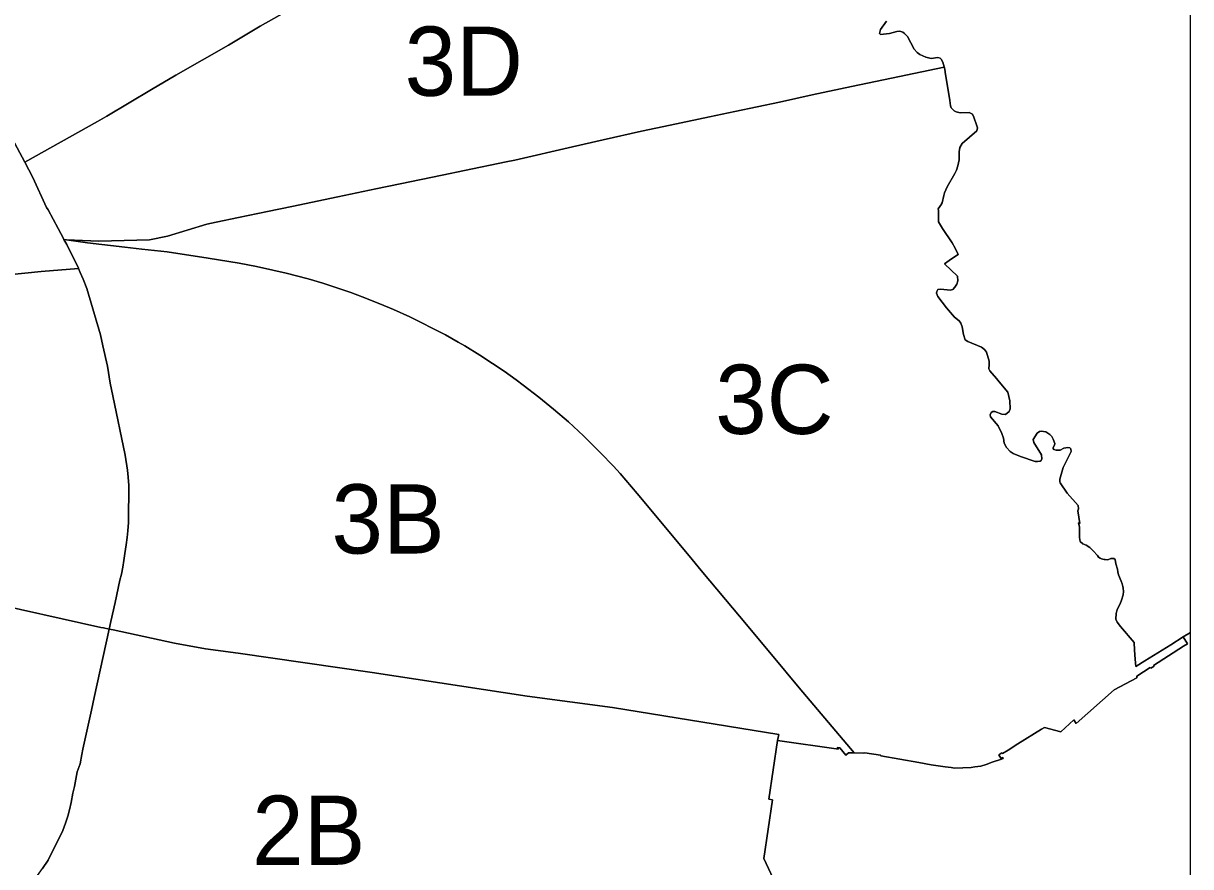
# Model space of a CAD drawing. Extents: x 152750 to 166250, y 378996 to 390000.
# Drawn here: x 162877 to 166250, y 382190 to 384626 of the extents above; entities that cross this region are included whole.
import ezdxf

# ---------------------------------------------------------------- set-up
doc = ezdxf.new("R2010")
doc.units = 0
doc.layers.add('BLT_Nummers', color=7, linetype='Continuous')
doc.layers.add('BLT_Shapes', color=7, linetype='Continuous')

msp = doc.modelspace()

# ---------------------------------------------------------------- linework, layer by layer
at = {"layer": 'BLT_Shapes'}
for p, q in [((165409.8, 384603.6), (165400.8, 384603.2)), ((165467.2, 384536), (165459.4, 384541.9)), ((165385.8, 384468.2), (165537.9, 384499.5)), ((165533.7, 384514.2), (165528.9, 384523.1)), ((165539.5, 384493.6), (165537.9, 384499.5)), ((165269.5, 384444.1), (165385.8, 384468.2)), ((165553.9, 384403.7), (165540.9, 384485)), ((165155.9, 384420), (165269.5, 384444.1)), ((165556.2, 384388.3), (165553.9, 384403.7)), ((165558.2, 384382.6), (165556.2, 384388.3)), ((165589.9, 384279.1), (165631.7, 384316)), ((165631.7, 384316), (165634.1, 384325)), ((164463.2, 384269.8), (164551.9, 384289.7)), ((165583.2, 384267.5), (165589.9, 384279.1)), ((162880.5, 384225.3), (162903.9, 384180.6)), ((165546.7, 384154.2), (165568.7, 384192.4)), ((163966, 384163.1), (164086.8, 384187.9)), ((163652.7, 384097.4), (163785.6, 384125.3)), ((165529.8, 384104.2), (165530.3, 384105.2)), ((165530.3, 384105.2), (165532, 384108.1)), ((165521.6, 384052.6), (165520.9, 384085.6)), ((165532.4, 384033.7), (165521.6, 384052.6)), ((163001.2, 384001.3), (162994.1, 384001.6)), ((162994.1, 384001.6), (163001.2, 384001.3)), ((163001.2, 384001.3), (163094.9, 383997.5)), ((165564.5, 383949.7), (165577.8, 383959.1)), ((163500.2, 383933.6), (163550, 383923.9)), ((163550, 383923.9), (163597.7, 383913.6)), ((165539.1, 383931.7), (165552.5, 383941.2)), ((165552.5, 383941.2), (165564.5, 383949.7)), ((163035.7, 383918.7), (162928.6, 383909.3)), ((163036.4, 383918.8), (163035.7, 383918.7)), ((163597.7, 383913.6), (163635.7, 383904.5)), ((163049.4, 383887.3), (163059.9, 383860.1)), ((163059.9, 383860.1), (163099.2, 383726.8)), ((163741.9, 383875.8), (163788.4, 383860.8)), ((165519, 383857.9), (165528.4, 383858.8)), ((165528.4, 383858.8), (165554.7, 383855.9)), ((165554.7, 383855.9), (165562.7, 383857.8)), ((164024.3, 383763.4), (164062.1, 383744.4)), ((165585.7, 383760), (165581.3, 383767)), ((165589.3, 383750), (165585.7, 383760)), ((165654.4, 383683.9), (165646, 383691.2)), ((165660.2, 383676.1), (165654.4, 383683.9)), ((164232.8, 383644.1), (164266, 383621.7)), ((164266, 383621.7), (164300.8, 383597)), ((165669.4, 383622.3), (165666.5, 383628.4)), ((164300.8, 383597), (164321.2, 383581.4)), ((165670.7, 383496), (165673.1, 383502)), ((165673.1, 383502), (165678.2, 383505.4)), ((165678.2, 383505.4), (165684, 383504.9)), ((165684, 383504.9), (165704.4, 383497.8)), ((165704.4, 383497.8), (165715.4, 383496.5)), ((165715.4, 383496.5), (165725.9, 383505)), ((165725.9, 383505), (165728.2, 383513.3)), ((164495.1, 383435.3), (164544.7, 383385.3)), ((165852.7, 383398.4), (165852.5, 383401.6)), ((165854.5, 383395.5), (165852.7, 383398.4)), ((165861.7, 383393.5), (165854.5, 383395.5)), ((165873.2, 383393.4), (165861.7, 383393.5)), ((165883.4, 383398.9), (165873.2, 383393.4)), ((165894.9, 383401.3), (165883.4, 383398.9)), ((165900.7, 383400.1), (165894.9, 383401.3)), ((165903.4, 383397.3), (165900.7, 383400.1)), ((165820.4, 383368.8), (165817.9, 383363.4)), ((164601.1, 383325.7), (164650.6, 383267.9)), ((163180.4, 383184.8), (163178.6, 383160.6)), ((163180.2, 383207.9), (163180.4, 383184.8)), ((163178.6, 383160.6), (163176.2, 383141.4)), ((165984.1, 383084.6), (165980.9, 383089.1)), ((165988.5, 383081.1), (165984.1, 383084.6)), ((166028, 383080.9), (166019.4, 383080.3)), ((166031.5, 383078.1), (166028, 383080.9)), ((163163.8, 383055.1), (163160, 383035)), ((166002.7, 383077.4), (166000, 383077.9)), ((166034, 383065), (166031.5, 383078.1)), ((163160, 383035), (163155.9, 383017.8)), ((166054.1, 383000), (166052.4, 383007.6)), ((166034.1, 382905.3), (166034.9, 382921.6)), ((166034.9, 382921.6), (166036.8, 382929.1)), ((163124.9, 382876.6), (163081.1, 382679)), ((163129.7, 382898.4), (163124.9, 382876.6)), ((166086.5, 382837.7), (166047.1, 382884.5)), ((166240.7, 382834.4), (166228.6, 382853.8)), ((166143.1, 382771.7), (166229.2, 382827.4)), ((166229.2, 382827.4), (166240.7, 382834.4)), ((163497.5, 382806.9), (163884.9, 382751.3)), ((166091.5, 382768.3), (166089.9, 382789.7)), ((163884.9, 382751.3), (164332.9, 382682.8)), ((166094.9, 382741), (166133.2, 382765.3)), ((166094.8, 382735.7), (166094.9, 382741)), ((165277.2, 382519.1), (165118.8, 382707.3)), ((165818.7, 382587.2), (165827.3, 382592.1)), ((165030.8, 382385.2), (165056.4, 382554.4)), ((163045.7, 382514.5), (163041, 382487.9)), ((163048.3, 382529.9), (163045.7, 382514.5)), ((165261.7, 382519.5), (165277.2, 382519.1)), ((165277.3, 382519.1), (165304.3, 382518.5)), ((165500.5, 382485), (165540.4, 382479.1)), ((165540.4, 382479.1), (165557.5, 382477)), ((165615.3, 382476.9), (165626.7, 382478.3)), ((165703.4, 382500.5), (165707.8, 382502.7)), ((163014.5, 382375.9), (163009.8, 382354.3)), ((163020.1, 382402.5), (163014.5, 382375.9)), ((165017, 382214.3), (165041.9, 382383.4)), ((163004.8, 382336.6), (162998.6, 382316.2)), ((163009.8, 382354.3), (163004.8, 382336.6)), ((162948.6, 382208.9), (162932.1, 382185.3))]:
    msp.add_line(p, q, dxfattribs=at)
for points in [[(165370.7, 384632.6), (165353.9, 384608.6), (165350.4, 384596.6), (165353.5, 384594.1), (165379.5, 384597.2), (165400.8, 384603.2), (165409.8, 384603.6), (165418.3, 384600.9), (165423.4, 384597.2), (165432.2, 384588.1), (165450.8, 384552), (165459.4, 384541.9), (165467.2, 384536), (165484.4, 384528.6), (165500, 384524.7), (165519.1, 384527.6), (165526.3, 384525.9), (165528.9, 384523.1), (165533.7, 384514.2), (165537.5, 384500.7), (165539.5, 384493.6), (165540.8, 384485.3), (165540.9, 384485), (165553.9, 384403.7), (165556.2, 384388.3), (165558.2, 384382.6), (165566.4, 384373.7), (165571.9, 384371.1), (165584.1, 384368.2), (165609.7, 384369.2), (165619.7, 384364), (165623.1, 384355), (165632.4, 384330.6), (165634.1, 384325), (165631.7, 384316), (165589.9, 384279.1), (165583.2, 384267.5), (165581.2, 384255.3), (165581, 384250), (165580.7, 384232.4), (165577.5, 384215.2), (165573.2, 384202), (165568.7, 384192.4), (165546.7, 384154.2), (165539.1, 384136.6), (165537.2, 384129.3), (165532, 384108.1), (165530.3, 384105.2), (165529.8, 384104.2), (165520.8, 384090.9), (165520.9, 384085.6), (165521.6, 384052.6), (165532.4, 384033.7), (165560.8, 383992.5), (165569, 383977.4), (165569.4, 383976.7), (165577.8, 383959.1), (165564.5, 383949.7), (165552.5, 383941.2), (165539.1, 383931.7), (165576.1, 383896.1), (165577.2, 383883), (165574.1, 383872.9), (165568.6, 383864), (165562.7, 383857.8), (165554.7, 383855.9), (165528.4, 383858.8), (165519, 383857.9), (165516.2, 383851.5), (165515.6, 383847), (165519.6, 383837.8), (165544.7, 383804.5), (165567.9, 383777.4), (165581.3, 383767), (165585.7, 383760), (165589.3, 383750), (165593.6, 383727.6), (165598.1, 383712.6), (165605.9, 383707), (165646, 383691.2), (165654.4, 383683.9), (165660.2, 383676.1), (165667.4, 383650.3), (165668.1, 383640.7), (165666.5, 383628.4), (165669.4, 383622.3), (165689.4, 383600), (165696.8, 383590.6), (165721.3, 383560.9), (165727.4, 383536.1), (165728.2, 383513.3), (165725.9, 383505), (165715.4, 383496.5), (165704.4, 383497.8), (165684, 383504.9), (165678.2, 383505.4), (165673.1, 383502), (165670.7, 383496), (165671.9, 383489.4), (165693.8, 383463.5), (165704.6, 383441.2), (165708.9, 383428.2), (165711.4, 383413.7), (165718.2, 383401.6), (165728.4, 383389.5), (165737.4, 383383.6), (165758.5, 383375), (165800.7, 383361), (165807.4, 383360.3), (165814.8, 383361.3), (165817.9, 383363.4), (165820.4, 383368.8), (165818.6, 383379.9), (165796.5, 383415.8), (165795.3, 383424.2), (165806.4, 383442.8), (165813.2, 383447.7), (165818.3, 383448.6), (165831.9, 383446.5), (165843, 383439.1), (165848.6, 383432.9), (165852.9, 383425.7), (165857.1, 383412.3), (165856.2, 383408.1), (165852.5, 383401.6), (165852.7, 383398.4), (165854.5, 383395.5), (165861.7, 383393.5), (165873.2, 383393.4), (165883.4, 383398.9), (165894.9, 383401.3), (165900.7, 383400.1), (165903.4, 383397.3), (165904.8, 383389.7), (165881.7, 383343), (165871.8, 383309.3), (165871.8, 383302.9), (165872.6, 383299), (165893, 383269.4), (165924.9, 383233.8), (165925.9, 383223.6), (165923.5, 383218), (165929.5, 383181.3), (165926.3, 383183.1), (165928.3, 383171.5), (165928.5, 383141.1), (165930.9, 383129.8), (165938.4, 383123.1), (165947.9, 383118.6), (165958.2, 383112.5), (165968.5, 383102.9), (165980.9, 383089.1), (165984.1, 383084.6), (165988.5, 383081.1), (165992.8, 383079.1), (166000, 383077.9), (166002.7, 383077.4), (166010.5, 383076.8), (166019.4, 383080.3), (166028, 383080.9), (166031.5, 383078.1), (166034, 383065), (166038.7, 383049.8), (166039.4, 383041.9), (166041.5, 383033), (166048.9, 383015.2), (166052.4, 383007.6), (166054.1, 383000), (166055.3, 382994.5), (166055.9, 382985.4), (166054.8, 382975.7), (166050.3, 382960.3), (166045.9, 382949.2), (166038.7, 382935.2), (166036.8, 382929.1), (166034.9, 382921.6), (166034.1, 382905.3), (166037.2, 382896.4), (166047.1, 382884.5), (166086.5, 382837.7), (166087.9, 382815.9), (166089.9, 382789.7), (166091.5, 382768.3), (166117.4, 382784.5), (166192.9, 382831.5), (166228.6, 382853.8), (166250, 382867.2), (166250, 386812.5)], [(165034.1, 385170.8), (164943.2, 385157.8), (164918.8, 385154.9), (164764.2, 385130.5), (164713.3, 385120.8), (164611.1, 385098.7), (164530.5, 385081), (164429.9, 385049.5), (164371.3, 385029.6), (164261.9, 384987.6), (164212.2, 384967.1), (164157.5, 384943.4), (164090.1, 384911.9), (164005, 384866), (163859.2, 384786.4), (163561.4, 384617.8), (163469.7, 384563.7), (163317.7, 384476.3), (163247.4, 384435), (163117.5, 384358.5), (163090.9, 384342.8), (162880.5, 384225.3)], [(163247.4, 384435), (163317.7, 384476.3), (163469.7, 384563.7), (163561.4, 384617.8), (163859.2, 384786.4), (164005, 384866), (164090.1, 384911.9), (164157.5, 384943.4)], [(165350.4, 384596.6), (165353.9, 384608.6), (165370.7, 384632.6)], [(165400.8, 384603.2), (165379.5, 384597.2), (165353.5, 384594.1), (165350.4, 384596.6)], [(165423.4, 384597.2), (165418.3, 384600.9), (165409.8, 384603.6)], [(165459.4, 384541.9), (165450.8, 384552), (165432.2, 384588.1), (165423.4, 384597.2)], [(165528.9, 384523.1), (165526.3, 384525.9), (165519.1, 384527.6), (165500, 384524.7), (165484.4, 384528.6), (165467.2, 384536)], [(165537.9, 384499.5), (165385.8, 384468.2), (165269.5, 384444.1), (165155.9, 384420), (165062.2, 384398.7), (164933, 384371.7), (164859.2, 384356.1), (164745.7, 384331.9), (164662.6, 384315.3), (164551.9, 384289.7), (164463.2, 384269.8), (164296.9, 384231), (164272.2, 384226.4), (164151.9, 384201.7), (164086.8, 384187.9), (163966, 384163.1), (163895.4, 384148.3), (163785.6, 384125.3), (163652.7, 384097.4), (163581.9, 384082.8), (163498.2, 384065.4), (163434, 384052), (163407, 384045.9), (163292.9, 384011.8), (163241.1, 384001.1), (163094.9, 383997.5), (163001.2, 384001.3)], [(165537.9, 384499.5), (165537.5, 384500.7), (165533.7, 384514.2)], [(165540.9, 384485), (165540.8, 384485.3), (165539.5, 384493.6)], [(162880.5, 384225.3), (163090.9, 384342.8), (163117.5, 384358.5), (163247.4, 384435)], [(164933, 384371.7), (165062.2, 384398.7), (165155.9, 384420)], [(162783.5, 384391.8), (162801.7, 384361.3), (162836.7, 384307.9), (162880.5, 384225.3)], [(164745.7, 384331.9), (164859.2, 384356.1), (164933, 384371.7)], [(165609.7, 384369.2), (165584.1, 384368.2), (165571.9, 384371.1), (165566.4, 384373.7), (165558.2, 384382.6)], [(165623.1, 384355), (165619.7, 384364), (165609.7, 384369.2)], [(164551.9, 384289.7), (164662.6, 384315.3), (164745.7, 384331.9)], [(165634.1, 384325), (165632.4, 384330.6), (165623.1, 384355)], [(162880.5, 384225.3), (162836.7, 384307.9)], [(164272.2, 384226.4), (164296.9, 384231), (164463.2, 384269.8)], [(165577.5, 384215.2), (165580.7, 384232.4), (165581, 384250), (165581.2, 384255.3), (165583.2, 384267.5)], [(164086.8, 384187.9), (164151.9, 384201.7), (164272.2, 384226.4)], [(162994.1, 384001.6), (162992.4, 384004.7), (162977, 384033.3), (162947.9, 384087.4), (162943.4, 384094.5), (162903.9, 384180.6), (162880.5, 384225.3)], [(165568.7, 384192.4), (165573.2, 384202), (165577.5, 384215.2)], [(162903.9, 384180.6), (162943.4, 384094.5), (162947.9, 384087.4)], [(163785.6, 384125.3), (163895.4, 384148.3), (163966, 384163.1)], [(165532, 384108.1), (165537.2, 384129.3), (165539.1, 384136.6), (165546.7, 384154.2)], [(163498.2, 384065.4), (163581.9, 384082.8), (163652.7, 384097.4)], [(165520.9, 384085.6), (165520.8, 384090.9), (165529.8, 384104.2)], [(162947.9, 384087.4), (162977, 384033.3), (162992.4, 384004.7), (162994.1, 384001.6)], [(163407, 384045.9), (163434, 384052), (163498.2, 384065.4)], [(163094.9, 383997.5), (163241.1, 384001.1), (163292.9, 384011.8), (163407, 384045.9)], [(165569, 383977.4), (165560.8, 383992.5), (165532.4, 384033.7)], [(163036.4, 383918.8), (163017.9, 383956.3), (163011.2, 383969.7), (163002.1, 383987.4), (162994.1, 384001.6)], [(162994.1, 384001.6), (163002.1, 383987.4), (163011.2, 383969.7), (163017.9, 383956.3), (163036.4, 383918.8)], [(165118.8, 382707.3), (165038.8, 382803.3), (164946.5, 382913.5), (164905.9, 382962.4), (164835.9, 383045.9), (164809.4, 383077.6), (164719, 383186.6), (164650.6, 383267.9), (164601.1, 383325.7), (164581.9, 383347.3), (164544.7, 383385.3), (164495.1, 383435.3), (164452.2, 383474.9), (164409, 383512.1), (164366.3, 383546.9), (164321.2, 383581.4), (164300.8, 383597), (164266, 383621.7), (164232.8, 383644.1), (164195.8, 383667.8), (164152.1, 383694.4), (164132.9, 383705.6), (164096.3, 383726.8), (164062.1, 383744.4), (164024.3, 383763.4), (163993.9, 383778.6), (163946, 383799.6), (163907, 383816.4), (163856, 383836.6), (163823, 383848.9), (163788.4, 383860.8), (163741.9, 383875.8), (163699.4, 383888.3), (163635.7, 383904.5), (163597.7, 383913.6), (163550, 383923.9), (163500.2, 383933.6), (163410.3, 383948.5), (163291.9, 383966.2), (163218.9, 383974.4), (163170.3, 383979.8), (163061.7, 383992.8), (163001.2, 384001.3)], [(163001.2, 384001.3), (163061.7, 383992.8), (163170.3, 383979.8)], [(163170.3, 383979.8), (163218.9, 383974.4), (163291.9, 383966.2)], [(163291.9, 383966.2), (163410.3, 383948.5), (163500.2, 383933.6)], [(165577.8, 383959.1), (165569.4, 383976.7), (165569, 383977.4)], [(165574.1, 383872.9), (165577.2, 383883), (165576.1, 383896.1), (165539.1, 383931.7)], [(162606.3, 383864.8), (162744, 383890), (162833.8, 383899.6), (162928.6, 383909.3), (163035.7, 383918.7), (163036.4, 383918.8)], [(162928.6, 383909.3), (162833.8, 383899.6), (162744, 383890), (162606.3, 383864.8)], [(163124.9, 382876.6), (163129.7, 382898.4), (163141.7, 382953.1), (163155.9, 383017.8), (163160, 383035), (163163.8, 383055.1), (163167.4, 383075.2), (163170.3, 383095.3), (163173.9, 383120.1), (163176.2, 383141.4), (163178.6, 383160.6), (163180.4, 383184.8), (163180.2, 383207.9), (163181.1, 383272.3), (163181.4, 383291.5), (163179.9, 383315.2), (163177.3, 383335.6), (163171.1, 383378.7), (163135.3, 383550.2), (163127.1, 383587.4), (163120, 383635.8), (163106.7, 383694.7), (163099.2, 383726.8), (163059.9, 383860.1), (163049.4, 383887.3), (163041.2, 383906.8), (163035.7, 383918.7)], [(163035.7, 383918.7), (163041.2, 383906.8), (163049.4, 383887.3)], [(163635.7, 383904.5), (163699.4, 383888.3), (163741.9, 383875.8)], [(163788.4, 383860.8), (163823, 383848.9), (163856, 383836.6)], [(165515.6, 383847), (165516.2, 383851.5), (165519, 383857.9)], [(165562.7, 383857.8), (165568.6, 383864), (165574.1, 383872.9)], [(163856, 383836.6), (163907, 383816.4), (163946, 383799.6), (163993.9, 383778.6), (164024.3, 383763.4)], [(165581.3, 383767), (165567.9, 383777.4), (165544.7, 383804.5), (165519.6, 383837.8), (165515.6, 383847)], [(163099.2, 383726.8), (163106.7, 383694.7), (163120, 383635.8), (163127.1, 383587.4)], [(164062.1, 383744.4), (164096.3, 383726.8), (164132.9, 383705.6), (164152.1, 383694.4), (164195.8, 383667.8), (164232.8, 383644.1)], [(165598.1, 383712.6), (165593.6, 383727.6), (165589.3, 383750)], [(165646, 383691.2), (165605.9, 383707), (165598.1, 383712.6)], [(165666.5, 383628.4), (165668.1, 383640.7), (165667.4, 383650.3), (165660.2, 383676.1)], [(165728.2, 383513.3), (165727.4, 383536.1), (165721.3, 383560.9), (165696.8, 383590.6), (165689.4, 383600), (165669.4, 383622.3)], [(163127.1, 383587.4), (163135.3, 383550.2), (163171.1, 383378.7)], [(164321.2, 383581.4), (164366.3, 383546.9), (164409, 383512.1)], [(164409, 383512.1), (164452.2, 383474.9), (164495.1, 383435.3)], [(165708.9, 383428.2), (165704.6, 383441.2), (165693.8, 383463.5), (165671.9, 383489.4), (165670.7, 383496)], [(165817.9, 383363.4), (165814.8, 383361.3), (165807.4, 383360.3), (165800.7, 383361), (165758.5, 383375), (165737.4, 383383.6), (165728.4, 383389.5), (165718.2, 383401.6), (165711.4, 383413.7), (165708.9, 383428.2)], [(165857.1, 383412.3), (165852.9, 383425.7), (165848.6, 383432.9), (165843, 383439.1), (165831.9, 383446.5), (165818.3, 383448.6), (165813.2, 383447.7), (165806.4, 383442.8), (165795.3, 383424.2), (165796.5, 383415.8)], [(164544.7, 383385.3), (164581.9, 383347.3), (164601.1, 383325.7)], [(165796.5, 383415.8), (165818.6, 383379.9), (165820.4, 383368.8)], [(165852.5, 383401.6), (165856.2, 383408.1), (165857.1, 383412.3)], [(165871.8, 383302.9), (165871.8, 383309.3), (165881.7, 383343), (165904.8, 383389.7), (165903.4, 383397.3)], [(163171.1, 383378.7), (163177.3, 383335.6), (163179.9, 383315.2), (163181.4, 383291.5), (163181.1, 383272.3), (163180.2, 383207.9)], [(165893, 383269.4), (165872.6, 383299), (165871.8, 383302.9)], [(164650.6, 383267.9), (164719, 383186.6), (164809.4, 383077.6), (164835.9, 383045.9)], [(165923.5, 383218), (165925.9, 383223.6), (165924.9, 383233.8), (165893, 383269.4)], [(165930.9, 383129.8), (165928.5, 383141.1), (165928.3, 383171.5), (165926.3, 383183.1), (165929.5, 383181.3), (165923.5, 383218)], [(163176.2, 383141.4), (163173.9, 383120.1), (163170.3, 383095.3), (163167.4, 383075.2), (163163.8, 383055.1)], [(165980.9, 383089.1), (165968.5, 383102.9), (165958.2, 383112.5), (165947.9, 383118.6), (165938.4, 383123.1), (165930.9, 383129.8)], [(166000, 383077.9), (165992.8, 383079.1), (165988.5, 383081.1)], [(166019.4, 383080.3), (166010.5, 383076.8), (166002.7, 383077.4)], [(164835.9, 383045.9), (164905.9, 382962.4), (164946.5, 382913.5), (165038.8, 382803.3), (165118.8, 382707.3)], [(166041.5, 383033), (166039.4, 383041.9), (166038.7, 383049.8), (166034, 383065)], [(163155.9, 383017.8), (163141.7, 382953.1), (163129.7, 382898.4)], [(166052.4, 383007.6), (166048.9, 383015.2), (166041.5, 383033)], [(163124.9, 382876.6), (163107.8, 382880.2), (163100.9, 382881.7), (162756.1, 382958.4), (162582.8, 382996), (162548.9, 383003.9)], [(166050.3, 382960.3), (166054.8, 382975.7), (166055.9, 382985.4)], [(166055.9, 382985.4), (166055.3, 382994.5), (166054.1, 383000)], [(162756.1, 382958.4), (163100.9, 382881.7), (163107.8, 382880.2), (163124.9, 382876.6)], [(166036.8, 382929.1), (166038.7, 382935.2), (166045.9, 382949.2), (166050.3, 382960.3)], [(162795.9, 382049.5), (162811, 382061.7), (162842, 382086.8), (162867.7, 382110.5), (162880.1, 382122.6), (162894.3, 382137.7), (162909.4, 382154.5), (162922.3, 382171.7), (162932.1, 382185.3), (162948.6, 382208.9), (162991.2, 382295.2), (162998.6, 382316.2), (163004.8, 382336.6), (163009.8, 382354.3), (163014.5, 382375.9), (163020.1, 382402.5), (163024, 382422.3), (163031.8, 382464.6), (163041, 382487.9), (163045.7, 382514.5), (163048.3, 382529.9), (163073.2, 382642.2), (163081.1, 382679), (163124.9, 382876.6)], [(165056.4, 382554.4), (165059.5, 382572.6), (164579, 382650), (164332.9, 382682.8), (163884.9, 382751.3), (163497.5, 382806.9), (163403, 382819.3), (163313, 382836.4), (163136.5, 382874.1), (163124.9, 382876.6)], [(163124.9, 382876.6), (163136.5, 382874.1), (163313, 382836.4)], [(166047.1, 382884.5), (166037.2, 382896.4), (166034.1, 382905.3)], [(166250, 379000), (166250, 382867.2), (166228.6, 382853.8), (166240.7, 382834.4), (166229.2, 382827.4), (166143.1, 382771.7), (166144.7, 382769.3), (166134.6, 382763.3), (166133.2, 382765.3), (166094.9, 382741), (166094.8, 382735.7), (166029.3, 382700.9), (165918.8, 382604.1), (165912.2, 382614.8), (165874.7, 382580.1), (165827.3, 382592.1), (165818.7, 382587.2), (165750.4, 382544.8), (165723.1, 382526.8), (165706.6, 382517.3), (165704.8, 382518.8), (165699, 382515.7), (165695.8, 382513.7), (165701.2, 382503.6), (165706.1, 382505.6), (165707.8, 382502.7), (165703.4, 382500.5), (165676, 382492.1), (165658.7, 382485.3), (165643.2, 382480.7), (165626.7, 382478.3), (165615.3, 382476.9), (165567.6, 382475), (165557.5, 382477), (165540.4, 382479.1), (165500.5, 382485), (165464.4, 382491.3), (165354.9, 382510.8), (165354.1, 382512.3), (165308.3, 382519), (165304.3, 382518.5), (165277.2, 382519.1), (165261.7, 382519.5), (165253.8, 382512.8), (165236, 382533.9), (165228.1, 382534.5), (165232, 382530.1), (165056.4, 382554.4), (165030.8, 382385.2), (165041.9, 382383.6), (165017, 382214.3), (165050.1, 382141.6)], [(166228.6, 382853.8), (166192.9, 382831.5), (166117.4, 382784.5), (166091.5, 382768.3)], [(163313, 382836.4), (163403, 382819.3), (163497.5, 382806.9)], [(166089.9, 382789.7), (166087.9, 382815.9), (166086.5, 382837.7)], [(166133.2, 382765.3), (166134.6, 382763.3), (166144.7, 382769.3), (166143.1, 382771.7)], [(165912.2, 382614.8), (165918.8, 382604.1), (166029.3, 382700.9), (166094.8, 382735.7)], [(163081.1, 382679), (163073.2, 382642.2), (163048.3, 382529.9)], [(164332.9, 382682.8), (164579, 382650), (165059.5, 382572.6), (165056.4, 382554.4)], [(165118.8, 382707.3), (165277.2, 382519.1), (165277.3, 382519.1)], [(165827.3, 382592.1), (165874.7, 382580.1), (165912.2, 382614.8)], [(165699, 382515.7), (165704.8, 382518.8), (165706.6, 382517.3), (165723.1, 382526.8), (165750.4, 382544.8), (165818.7, 382587.2)], [(165056.4, 382554.4), (165232, 382530.1), (165228.1, 382534.5), (165236, 382533.9), (165253.8, 382512.8), (165261.7, 382519.5)], [(165277.2, 382519.1), (165277.2, 382519.1)], [(165304.3, 382518.5), (165308.3, 382519), (165354.1, 382512.3)], [(165354.1, 382512.3), (165354.9, 382510.8), (165464.4, 382491.3), (165500.5, 382485)], [(165701.2, 382503.6), (165695.8, 382513.7), (165699, 382515.7)], [(165707.8, 382502.7), (165706.1, 382505.6), (165701.2, 382503.6)], [(163041, 382487.9), (163031.8, 382464.6), (163024, 382422.3), (163020.1, 382402.5)], [(165557.5, 382477), (165567.6, 382475), (165615.3, 382476.9)], [(165626.7, 382478.3), (165643.2, 382480.7), (165658.7, 382485.3), (165676, 382492.1), (165703.4, 382500.5)], [(165041.9, 382383.4), (165030.8, 382385.1), (165030.8, 382385.2)], [(165030.8, 382385.2), (165030.8, 382385.2)], [(162998.6, 382316.2), (162991.2, 382295.2), (162948.6, 382208.9)], [(165054.8, 382111.4), (165059, 382140.2), (165050, 382141.5), (165017, 382214.1), (165017, 382214.3)]]:
    msp.add_lwpolyline(points, dxfattribs=at)

# ---------------------------------------------------------------- texts
at = {"layer": 'BLT_Nummers'}
for s, p in [('3D', (163978.5, 384417.1)), ('3C', (164876.1, 383440.4)), ('3B', (163767.1, 383094.9)), ('2B', (163537.9, 382195.6))]:
    msp.add_text(s, height=200, dxfattribs=at).set_placement(p)

doc.saveas('drawing.dxf')
